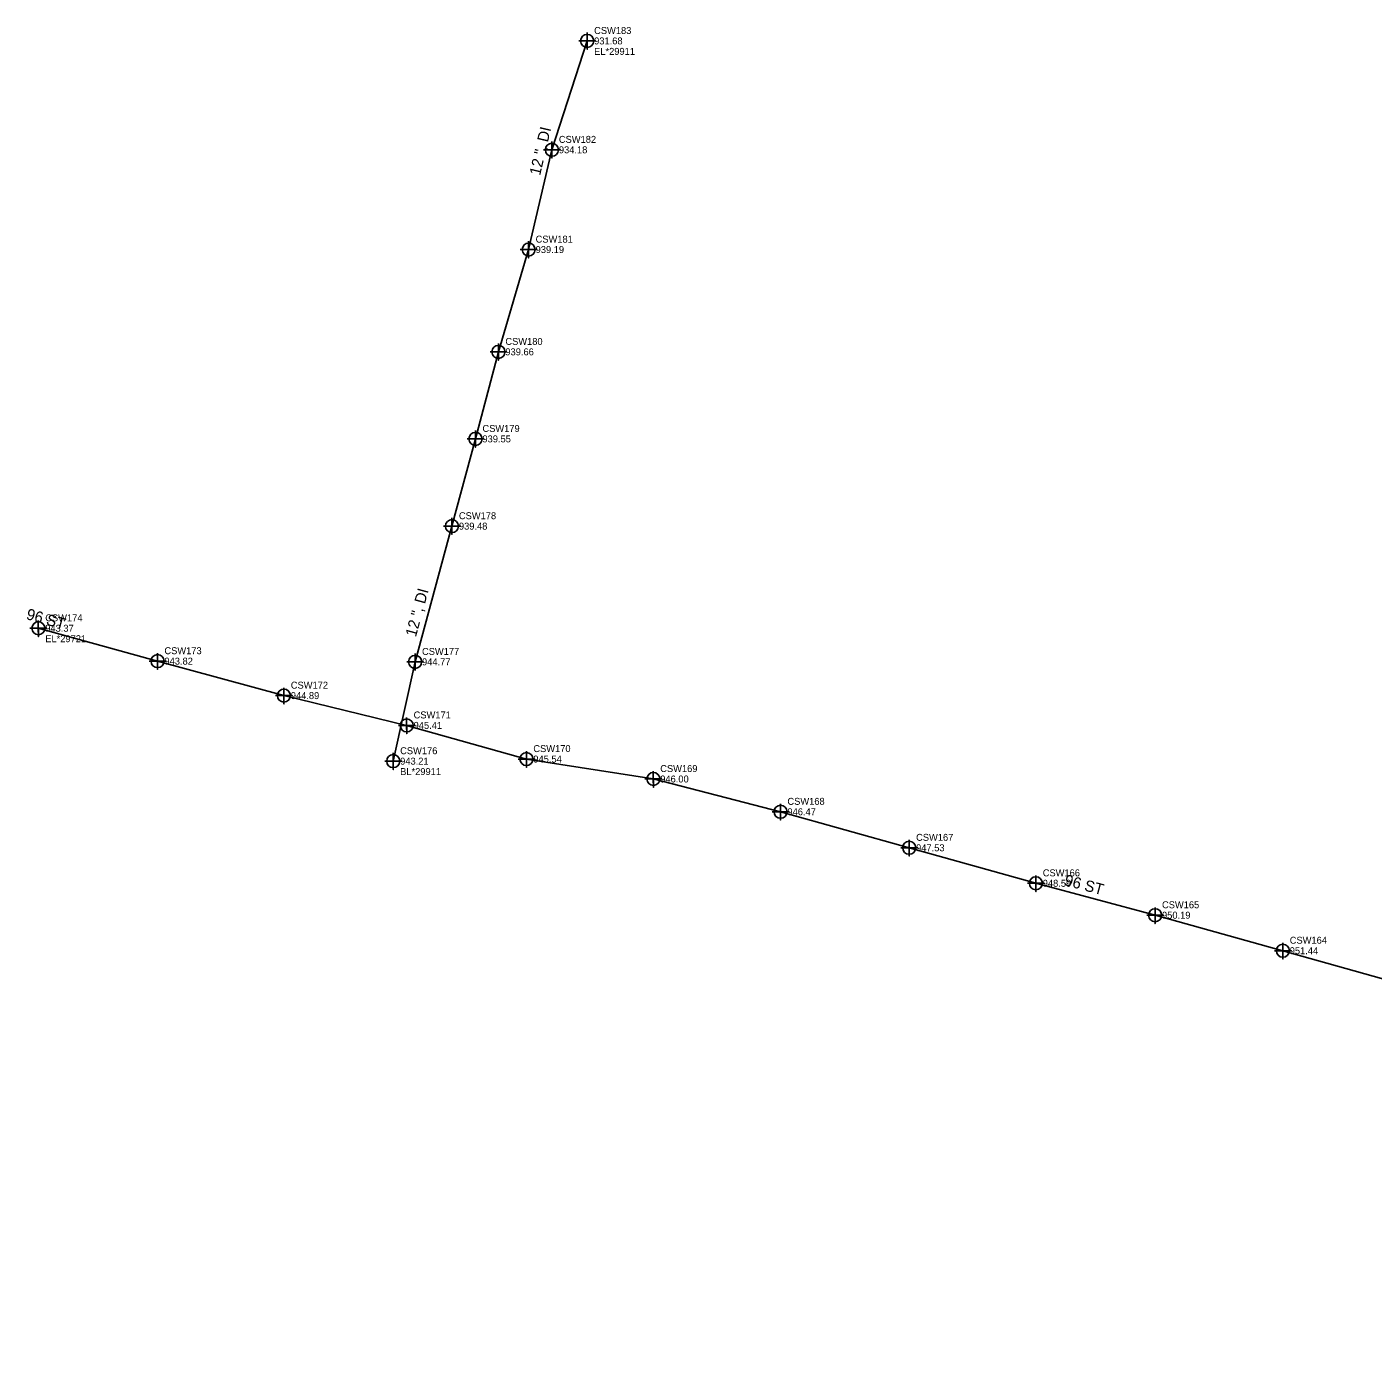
# Model space of a CAD drawing. Extents: x 1182504 to 1186036, y 573002 to 575111.
# Drawn here: x 1182504.4 to 1182988.2, y 574205.1 to 574684.9 of the extents above; entities that cross this region are included whole.
import ezdxf

# ---------------------------------------------------------------- set-up
doc = ezdxf.new("R2010")
doc.units = 0
for name, color, linetype in [('Exist Utilities Telephone UG Conduit SUE LOS B', 7, 'Continuous'), ('Exist Utilities Telephone UG Conduit SUE LOS B Cogo Comment', 7, 'Continuous'), ('Exist Utilities Telephone UG Conduit SUE LOS B Cogo Elevation', 7, 'Continuous'), ('Exist Utilities Telephone UG Conduit SUE LOS B Cogo Number', 7, 'Continuous'), ('Exist Utilities Telephone UG Conduit SUE LOS B Cogo Point CELL', 7, 'Continuous'), ('Exist Utilities Telephone UG Conduit SUE LOS B Text', 7, 'Continuous'), ('Exist Utilities Water UG Line SUE LOS B', 7, 'Continuous'), ('Exist Utilities Water UG Line SUE LOS B Cogo Comment', 7, 'Continuous'), ('Exist Utilities Water UG Line SUE LOS B Cogo Elevation', 7, 'Continuous'), ('Exist Utilities Water UG Line SUE LOS B Cogo Number', 7, 'Continuous'), ('Exist Utilities Water UG Line SUE LOS B Cogo Point CELL', 7, 'Continuous'), ('Exist Utilities Water UG Line SUE LOS B Text', 7, 'Continuous')]:
    doc.layers.add(name, color=color, linetype=linetype)

msp = doc.modelspace()

# ---------------------------------------------------------------- linework, layer by layer
at = {"layer": 'Exist Utilities Telephone UG Conduit SUE LOS B'}
msp.add_lwpolyline([(1182508.5, 574468.79), (1182551.34, 574456.98), (1182596.76, 574444.59), (1182640.9, 574433.89), (1182683.93, 574421.8), (1182729.54, 574414.63), (1182775.26, 574402.85), (1182821.5, 574389.91), (1182867.02, 574377.15), (1182909.89, 574365.68), (1182955.8, 574352.93), (1183001.1, 574340.19), (1183047.8, 574326.93), (1183094.08, 574314.14), (1183140.16, 574301.96), (1183184.2, 574290.24), (1183230.46, 574277.8), (1183276.74, 574264.86), (1183322.88, 574252.13), (1183369.36, 574239.84), (1183416.41, 574227.82), (1183461.9, 574217.61), (1183507.97, 574205.1)], dxfattribs=at)
at = {"layer": 'Exist Utilities Telephone UG Conduit SUE LOS B Cogo Point CELL'}
for points in [[(1182508.48, 574471.61), (1182508.52, 574465.79), (1182508.5, 574468.79), (1182511.52, 574468.79), (1182505.52, 574468.79)], [(1182551.33, 574459.79), (1182551.36, 574453.98), (1182551.34, 574456.98), (1182554.36, 574456.98), (1182548.36, 574456.98)], [(1182596.75, 574447.41), (1182596.78, 574441.59), (1182596.76, 574444.59), (1182599.78, 574444.59), (1182593.78, 574444.59)], [(1182640.88, 574436.71), (1182640.92, 574430.89), (1182640.9, 574433.89), (1182643.92, 574433.89), (1182637.92, 574433.89)], [(1182683.92, 574424.61), (1182683.95, 574418.8), (1182683.93, 574421.8), (1182686.95, 574421.8), (1182680.95, 574421.8)], [(1182729.53, 574417.44), (1182729.56, 574411.63), (1182729.54, 574414.63), (1182732.56, 574414.63), (1182726.56, 574414.63)], [(1182775.25, 574405.66), (1182775.28, 574399.85), (1182775.26, 574402.85), (1182778.28, 574402.85), (1182772.28, 574402.85)], [(1182821.48, 574392.72), (1182821.52, 574386.91), (1182821.5, 574389.91), (1182824.52, 574389.91), (1182818.52, 574389.91)], [(1182867, 574379.96), (1182867.04, 574374.15), (1182867.02, 574377.15), (1182870.04, 574377.15), (1182864.04, 574377.15)], [(1182909.87, 574368.5), (1182909.9, 574362.68), (1182909.89, 574365.68), (1182912.9, 574365.68), (1182906.9, 574365.68)], [(1182955.79, 574355.75), (1182955.82, 574349.93), (1182955.8, 574352.93), (1182958.82, 574352.93), (1182952.82, 574352.93)]]:
    msp.add_lwpolyline(points, dxfattribs=at)
for centre in [(1182508.52, 574468.79), (1182551.36, 574456.98), (1182596.78, 574444.59), (1182640.92, 574433.89), (1182683.95, 574421.8), (1182729.56, 574414.63), (1182775.28, 574402.85), (1182821.52, 574389.91), (1182867.04, 574377.15), (1182909.9, 574365.68), (1182955.82, 574352.93)]:
    msp.add_circle(centre, 2.34, dxfattribs=at)
at = {"layer": 'Exist Utilities Water UG Line SUE LOS B'}
msp.add_lwpolyline([(1182636.06, 574421.04), (1182643.92, 574456.72), (1182657.18, 574505.49), (1182665.64, 574536.84), (1182673.88, 574568.12), (1182684.75, 574604.87), (1182693.11, 574640.73), (1182705.78, 574679.85)], dxfattribs=at)
at = {"layer": 'Exist Utilities Water UG Line SUE LOS B Cogo Point CELL'}
for points in [[(1182705.78, 574682.85), (1182705.78, 574676.85), (1182705.78, 574679.85), (1182708.78, 574679.85), (1182702.78, 574679.85)], [(1182693.11, 574643.73), (1182693.11, 574637.73), (1182693.11, 574640.73), (1182696.11, 574640.73), (1182690.11, 574640.73)], [(1182684.75, 574607.87), (1182684.75, 574601.87), (1182684.75, 574604.87), (1182687.75, 574604.87), (1182681.75, 574604.87)], [(1182673.88, 574571.12), (1182673.88, 574565.12), (1182673.88, 574568.12), (1182676.88, 574568.12), (1182670.88, 574568.12)], [(1182665.64, 574539.84), (1182665.64, 574533.84), (1182665.64, 574536.84), (1182668.64, 574536.84), (1182662.64, 574536.84)], [(1182657.18, 574508.49), (1182657.18, 574502.49), (1182657.18, 574505.49), (1182660.18, 574505.49), (1182654.18, 574505.49)], [(1182643.92, 574459.72), (1182643.92, 574453.72), (1182643.92, 574456.72), (1182646.92, 574456.72), (1182640.92, 574456.72)], [(1182636.06, 574424.04), (1182636.06, 574418.04), (1182636.06, 574421.04), (1182639.06, 574421.04), (1182633.06, 574421.04)]]:
    msp.add_lwpolyline(points, dxfattribs=at)
for centre in [(1182705.78, 574679.85), (1182693.11, 574640.73), (1182684.75, 574604.87), (1182673.88, 574568.12), (1182665.64, 574536.84), (1182657.18, 574505.49), (1182643.92, 574456.72), (1182636.06, 574421.04)]:
    msp.add_circle(centre, 2.34, dxfattribs=at)

# ---------------------------------------------------------------- texts
at = {"layer": 'Exist Utilities Telephone UG Conduit SUE LOS B Cogo Comment'}
msp.add_text('EL*29721', height=2.5, dxfattribs=at).set_placement((1182511, 574463.79))
at = {"layer": 'Exist Utilities Telephone UG Conduit SUE LOS B Cogo Elevation'}
for s, p in [('943.37', (1182511, 574467.54)), ('943.82', (1182553.84, 574455.73)), ('944.89', (1182599.26, 574443.34)), ('945.41', (1182643.4, 574432.64)), ('945.54', (1182686.43, 574420.55)), ('946.00', (1182732.04, 574413.38)), ('946.47', (1182777.76, 574401.6)), ('947.53', (1182824, 574388.66)), ('948.59', (1182869.52, 574375.9)), ('950.19', (1182912.39, 574364.43)), ('951.44', (1182958.3, 574351.68))]:
    msp.add_text(s, height=2.5, dxfattribs=at).set_placement(p)
at = {"layer": 'Exist Utilities Telephone UG Conduit SUE LOS B Cogo Number'}
for s, p in [('CSW174', (1182511, 574471.29)), ('CSW173', (1182553.84, 574459.48)), ('CSW172', (1182599.26, 574447.09)), ('CSW171', (1182643.4, 574436.39)), ('CSW170', (1182686.43, 574424.3)), ('CSW169', (1182732.04, 574417.13)), ('CSW168', (1182777.76, 574405.35)), ('CSW167', (1182824, 574392.41)), ('CSW166', (1182869.52, 574379.65)), ('CSW165', (1182912.39, 574368.18)), ('CSW164', (1182958.3, 574355.43))]:
    msp.add_text(s, height=2.5, dxfattribs=at).set_placement(p)
at = {"layer": 'Exist Utilities Telephone UG Conduit SUE LOS B Text'}
for rotation, p in [(344.5829, (1182503.9, 574472.13)), (345.0258, (1182877.02, 574376.54))]:
    msp.add_text('96 ST', height=4, rotation=rotation, dxfattribs=at).set_placement(p)
at = {"layer": 'Exist Utilities Water UG Line SUE LOS B Cogo Comment'}
for s, p in [('EL*29911', (1182708.28, 574674.85)), ('BL*29911', (1182638.56, 574416.04))]:
    msp.add_text(s, height=2.5, dxfattribs=at).set_placement(p)
at = {"layer": 'Exist Utilities Water UG Line SUE LOS B Cogo Elevation'}
for s, p in [('931.68', (1182708.28, 574678.6)), ('934.18', (1182695.61, 574639.48)), ('939.19', (1182687.25, 574603.62)), ('939.66', (1182676.38, 574566.87)), ('939.55', (1182668.14, 574535.59)), ('939.48', (1182659.68, 574504.24)), ('944.77', (1182646.42, 574455.47)), ('943.21', (1182638.56, 574419.79))]:
    msp.add_text(s, height=2.5, dxfattribs=at).set_placement(p)
at = {"layer": 'Exist Utilities Water UG Line SUE LOS B Cogo Number'}
for s, p in [('CSW183', (1182708.28, 574682.35)), ('CSW182', (1182695.61, 574643.23)), ('CSW181', (1182687.25, 574607.37)), ('CSW180', (1182676.38, 574570.62)), ('CSW179', (1182668.14, 574539.34)), ('CSW178', (1182659.68, 574507.99)), ('CSW177', (1182646.42, 574459.22)), ('CSW176', (1182638.56, 574423.54))]:
    msp.add_text(s, height=2.5, dxfattribs=at).set_placement(p)
at = {"layer": 'Exist Utilities Water UG Line SUE LOS B Text'}
for rotation, p in [(76.8823, (1182688.85, 574631.27)), (74.7931, (1182644.22, 574465.45))]:
    msp.add_text('12 ", DI', height=4, rotation=rotation, dxfattribs=at).set_placement(p)

doc.saveas('drawing.dxf')
